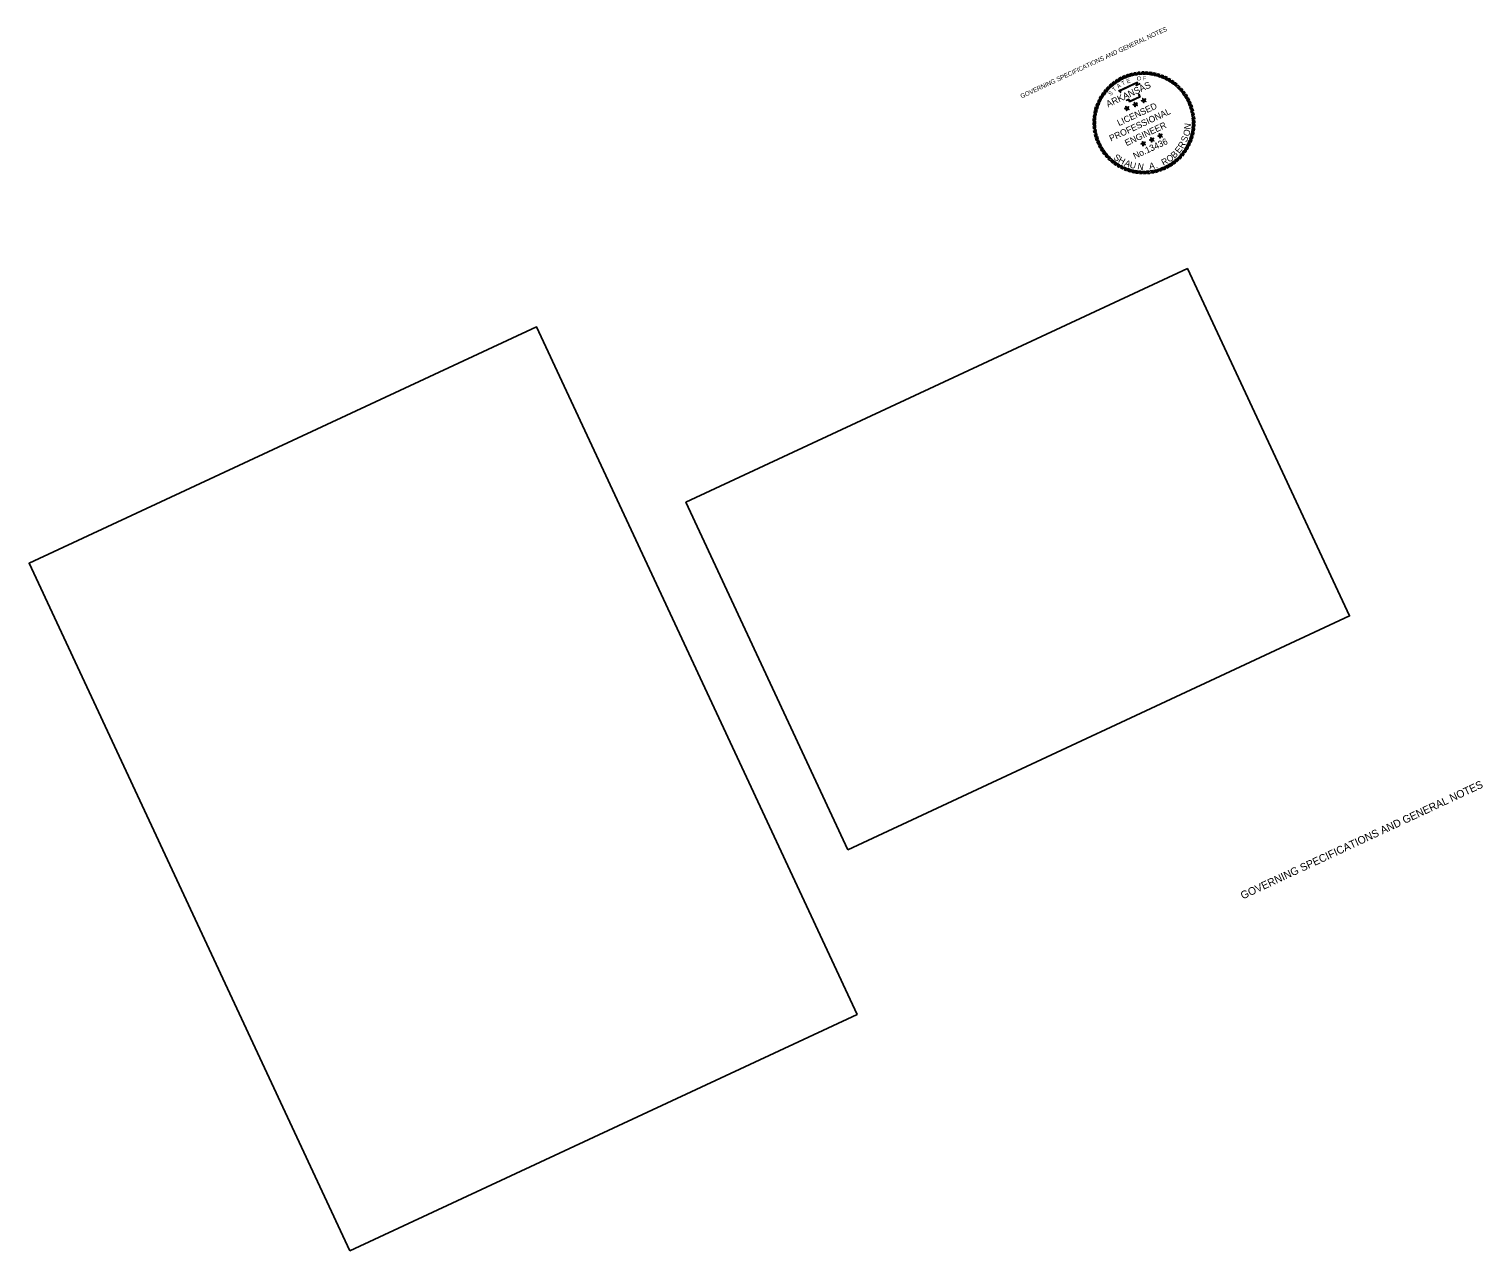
# Model space of a CAD drawing. Extents: x 757071 to 763666, y 1656563 to 1660766.
# Drawn here: x 760259 to 763666, y 1657902 to 1660766 of the extents above; entities that cross this region are included whole.
import ezdxf

# ---------------------------------------------------------------- set-up
doc = ezdxf.new("R2010")
doc.units = 0
for name, color, linetype in [('1', 7, 'Continuous'), ('60', 7, 'Continuous'), ('G-ANNO-SYMB', 7, 'Continuous')]:
    doc.layers.add(name, color=color, linetype=linetype)

msp = doc.modelspace()

# ---------------------------------------------------------------- linework, layer by layer
at = {"layer": '1'}
for points in [[(762178.2, 1658842.1), (763353.8, 1659390.3), (762973.9, 1660204.8), (761798.4, 1659656.7)], [(761010.6, 1657901.7), (762199.5, 1658456.1), (761447.8, 1660068.2), (760258.8, 1659513.8)]]:
    msp.add_lwpolyline(points, close=True, dxfattribs=at)
at = {"layer": 'G-ANNO-SYMB'}
for points in [[(762795, 1660637.6), (762791.2, 1660634.3), (762789.8, 1660625.2), (762793.7, 1660629.1)], [(762802.4, 1660643.4), (762798.3, 1660640.3), (762796.2, 1660631.4), (762800.4, 1660635)], [(762810.2, 1660648.6), (762805.9, 1660645.8), (762803.1, 1660637.1), (762807.6, 1660640.4)], [(762818.5, 1660653.1), (762813.9, 1660650.7), (762810.4, 1660642.2), (762815.2, 1660645.1)], [(762827, 1660657), (762822.3, 1660654.9), (762818.1, 1660646.8), (762823.1, 1660649.3)], [(762835.8, 1660660.1), (762830.9, 1660658.5), (762826.2, 1660650.7), (762831.3, 1660652.8)], [(762844.8, 1660662.6), (762839.9, 1660661.4), (762834.5, 1660654), (762839.8, 1660655.6)], [(762854, 1660664.4), (762849, 1660663.5), (762843, 1660656.6), (762848.4, 1660657.8)], [(762863.3, 1660665.4), (762858.2, 1660665), (762851.8, 1660658.5), (762857.2, 1660659.3)], [(762872.7, 1660665.7), (762867.6, 1660665.7), (762860.6, 1660659.7), (762866.1, 1660660.1)], [(762882.1, 1660665.3), (762876.9, 1660665.6), (762869.5, 1660660.3), (762875.1, 1660660.3)], [(762891.4, 1660664.2), (762886.3, 1660664.9), (762878.5, 1660660.1), (762884, 1660659.7)], [(762900.5, 1660662.3), (762895.5, 1660663.4), (762887.4, 1660659.2), (762892.9, 1660658.4)], [(762909.5, 1660659.7), (762904.6, 1660661.2), (762896.2, 1660657.7), (762901.6, 1660656.4)], [(762918.3, 1660656.4), (762913.5, 1660658.3), (762904.8, 1660655.4), (762910.1, 1660653.7)], [(762926.8, 1660652.4), (762922.2, 1660654.7), (762913.3, 1660652.5), (762918.4, 1660650.4)], [(762934.9, 1660647.8), (762930.5, 1660650.4), (762921.5, 1660649), (762926.4, 1660646.4)], [(762942.7, 1660642.5), (762938.5, 1660645.5), (762929.4, 1660644.8), (762934.1, 1660641.8)], [(762950, 1660636.7), (762946.1, 1660639.9), (762936.9, 1660639.9), (762941.4, 1660636.7)], [(762956.9, 1660630.3), (762953.2, 1660633.8), (762944.1, 1660634.6), (762948.3, 1660630.9)], [(762766, 1660601.3), (762763.7, 1660596.7), (762765.9, 1660587.8), (762768, 1660592.9)], [(762770.6, 1660609.4), (762768, 1660605), (762769.4, 1660596), (762772, 1660600.9)], [(762775.9, 1660617.2), (762772.9, 1660613), (762773.6, 1660603.9), (762776.5, 1660608.6)], [(762781.7, 1660624.5), (762778.4, 1660620.5), (762778.4, 1660611.4), (762781.7, 1660615.9)], [(762788.1, 1660631.3), (762784.5, 1660627.6), (762783.8, 1660618.5), (762787.4, 1660622.7)], [(762871.6, 1660598.7), (762869.8, 1660599.7), (762866.2, 1660598), (762870.1, 1660597.3)], [(762871.6, 1660598.7), (762872, 1660600.8), (762869.3, 1660603.7), (762869.8, 1660599.7)], [(762871.6, 1660598.7), (762873.7, 1660599), (762875.6, 1660602.4), (762872, 1660600.8)], [(762963.2, 1660623.3), (762959.8, 1660627.2), (762950.7, 1660628.6), (762954.6, 1660624.7)], [(762968.9, 1660616), (762965.8, 1660620.1), (762956.9, 1660622.2), (762960.5, 1660618)], [(762974.1, 1660608.1), (762971.3, 1660612.5), (762962.6, 1660615.3), (762965.9, 1660610.8)], [(762978.6, 1660599.9), (762976.2, 1660604.5), (762967.8, 1660608), (762970.6, 1660603.2)], [(762982.5, 1660591.4), (762980.4, 1660596.1), (762972.3, 1660600.3), (762974.8, 1660595.3)], [(762754.2, 1660565.8), (762753.5, 1660560.8), (762758.3, 1660553), (762758.7, 1660558.5)], [(762756.1, 1660575), (762755, 1660570), (762759.1, 1660561.9), (762760, 1660567.3)], [(762758.7, 1660584), (762757.2, 1660579.1), (762760.7, 1660570.7), (762762, 1660576.1)], [(762762, 1660592.8), (762760.1, 1660588), (762762.9, 1660579.3), (762764.7, 1660584.6)], [(762832.1, 1660580.3), (762830.3, 1660581.3), (762826.7, 1660579.6), (762830.6, 1660578.8)], [(762832.1, 1660580.3), (762832.5, 1660582.3), (762829.8, 1660585.2), (762830.3, 1660581.3)], [(762832.1, 1660580.3), (762830.6, 1660578.8), (762831.1, 1660574.9), (762833, 1660578.4)], [(762832.1, 1660580.3), (762834.2, 1660580.5), (762836.1, 1660584), (762832.5, 1660582.3)], [(762832.1, 1660580.3), (762833, 1660578.4), (762836.9, 1660577.6), (762834.2, 1660580.5)], [(762851.9, 1660589.5), (762850, 1660590.5), (762846.5, 1660588.8), (762850.3, 1660588.1)], [(762851.9, 1660589.5), (762852.3, 1660591.5), (762849.6, 1660594.4), (762850, 1660590.5)], [(762851.9, 1660589.5), (762850.3, 1660588.1), (762850.8, 1660584.1), (762852.7, 1660587.6)], [(762851.9, 1660589.5), (762853.9, 1660589.7), (762855.9, 1660593.2), (762852.3, 1660591.5)], [(762851.9, 1660589.5), (762852.7, 1660587.6), (762856.6, 1660586.8), (762853.9, 1660589.7)], [(762871.6, 1660598.7), (762870.1, 1660597.3), (762870.6, 1660593.4), (762872.5, 1660596.8)], [(762871.6, 1660598.7), (762872.5, 1660596.8), (762876.4, 1660596.1), (762873.7, 1660599)], [(762985.7, 1660582.6), (762984, 1660587.4), (762976.2, 1660592.2), (762978.3, 1660587.1)], [(762988.1, 1660573.6), (762986.9, 1660578.5), (762979.5, 1660583.9), (762981.2, 1660578.6)], [(762989.9, 1660564.3), (762989, 1660569.4), (762982.1, 1660575.3), (762983.4, 1660569.9)], [(762991, 1660555), (762990.5, 1660560.1), (762984, 1660566.6), (762984.9, 1660561.1)], [(762752.6, 1660547.2), (762752.7, 1660542.1), (762758.6, 1660535.1), (762758.2, 1660540.6)], [(762753.1, 1660556.5), (762752.7, 1660551.4), (762758.1, 1660544), (762758.1, 1660549.6)], [(762752.9, 1660537.8), (762753.4, 1660532.7), (762759.9, 1660526.2), (762759, 1660531.7)], [(762991.3, 1660545.7), (762991.2, 1660550.8), (762985.2, 1660557.8), (762985.7, 1660552.2)], [(762989.7, 1660527), (762990.4, 1660532.1), (762985.6, 1660539.9), (762985.2, 1660534.4)], [(762990.8, 1660536.3), (762991.2, 1660541.4), (762985.8, 1660548.8), (762985.8, 1660543.3)], [(762754, 1660528.5), (762754.9, 1660523.5), (762761.8, 1660517.5), (762760.5, 1660522.9)], [(762755.8, 1660519.3), (762757, 1660514.3), (762764.4, 1660509), (762762.7, 1660514.2)], [(762758.2, 1660510.3), (762759.9, 1660505.4), (762767.7, 1660500.6), (762765.6, 1660505.8)], [(762761.4, 1660501.5), (762763.5, 1660496.8), (762771.6, 1660492.6), (762769.1, 1660497.6)], [(762870.7, 1660497.5), (762868.9, 1660498.5), (762865.3, 1660496.8), (762869.2, 1660496)], [(762870.7, 1660497.5), (762871.1, 1660499.5), (762868.4, 1660502.4), (762868.9, 1660498.5)], [(762870.7, 1660497.5), (762869.2, 1660496), (762869.7, 1660492.1), (762871.6, 1660495.6)], [(762870.7, 1660497.5), (762872.8, 1660497.7), (762874.7, 1660501.2), (762871.1, 1660499.5)], [(762870.7, 1660497.5), (762871.6, 1660495.6), (762875.5, 1660494.8), (762872.8, 1660497.7)], [(762890.5, 1660506.7), (762888.7, 1660507.7), (762885.1, 1660506), (762889, 1660505.3)], [(762890.5, 1660506.7), (762890.9, 1660508.7), (762888.2, 1660511.6), (762888.7, 1660507.7)], [(762890.5, 1660506.7), (762889, 1660505.3), (762889.4, 1660501.3), (762891.4, 1660504.8)], [(762890.5, 1660506.7), (762892.5, 1660506.9), (762894.5, 1660510.4), (762890.9, 1660508.7)], [(762890.5, 1660506.7), (762891.4, 1660504.8), (762895.3, 1660504), (762892.5, 1660506.9)], [(762910.3, 1660515.9), (762908.4, 1660516.9), (762904.8, 1660515.2), (762908.7, 1660514.5)], [(762910.3, 1660515.9), (762910.7, 1660518), (762907.9, 1660520.9), (762908.4, 1660516.9)], [(762910.3, 1660515.9), (762908.7, 1660514.5), (762909.2, 1660510.6), (762911.1, 1660514)], [(762910.3, 1660515.9), (762912.3, 1660516.2), (762914.2, 1660519.6), (762910.7, 1660518)], [(762910.3, 1660515.9), (762911.1, 1660514), (762915, 1660513.3), (762912.3, 1660516.2)], [(762977.9, 1660491.6), (762980.2, 1660496.2), (762978, 1660505.1), (762975.9, 1660500)], [(762981.9, 1660500.1), (762983.8, 1660504.8), (762981, 1660513.5), (762979.2, 1660508.3)], [(762985.2, 1660508.8), (762986.7, 1660513.7), (762983.2, 1660522.2), (762981.9, 1660516.8)], [(762987.8, 1660517.8), (762988.9, 1660522.8), (762984.8, 1660531), (762983.9, 1660525.5)], [(762765.3, 1660492.9), (762767.7, 1660488.4), (762776.1, 1660484.9), (762773.3, 1660489.6)], [(762769.8, 1660484.7), (762772.6, 1660480.4), (762781.3, 1660477.6), (762778, 1660482.1)], [(762775, 1660476.9), (762778.1, 1660472.8), (762786.9, 1660470.7), (762783.4, 1660474.9)], [(762780.7, 1660469.5), (762784.1, 1660465.7), (762793.2, 1660464.2), (762789.2, 1660468.2)], [(762948.9, 1660455.2), (762952.7, 1660458.6), (762954.1, 1660467.6), (762950.2, 1660463.7)], [(762955.8, 1660461.5), (762959.4, 1660465.2), (762960.1, 1660474.3), (762956.5, 1660470.1)], [(762962.2, 1660468.4), (762965.5, 1660472.3), (762965.5, 1660481.5), (762962.2, 1660477)], [(762968, 1660475.7), (762971, 1660479.9), (762970.3, 1660489), (762967.4, 1660484.3)], [(762973.3, 1660483.4), (762975.9, 1660487.9), (762974.5, 1660496.9), (762971.9, 1660492)], [(762787, 1660462.6), (762790.7, 1660459), (762799.8, 1660458.3), (762795.6, 1660461.9)], [(762793.9, 1660456.2), (762797.8, 1660452.9), (762807, 1660452.9), (762802.5, 1660456.2)], [(762801.2, 1660450.3), (762805.4, 1660447.4), (762814.5, 1660448.1), (762809.8, 1660451)], [(762809, 1660445.1), (762813.4, 1660442.5), (762822.4, 1660443.9), (762817.5, 1660446.4)], [(762817.1, 1660440.5), (762821.7, 1660438.2), (762830.6, 1660440.3), (762825.5, 1660442.5)], [(762825.6, 1660436.5), (762830.4, 1660434.6), (762839.1, 1660437.4), (762833.8, 1660439.1)], [(762834.4, 1660433.2), (762839.3, 1660431.7), (762847.7, 1660435.2), (762842.3, 1660436.5)], [(762843.4, 1660430.6), (762848.4, 1660429.5), (762856.5, 1660433.6), (762851, 1660434.5)], [(762852.5, 1660428.7), (762857.6, 1660428), (762865.4, 1660432.8), (762859.9, 1660433.2)], [(762861.8, 1660427.5), (762867, 1660427.2), (762874.4, 1660432.6), (762868.8, 1660432.6)], [(762871.2, 1660427.1), (762876.3, 1660427.2), (762883.3, 1660433.1), (762877.8, 1660432.7)], [(762880.6, 1660427.4), (762885.7, 1660427.9), (762892.1, 1660434.4), (762886.7, 1660433.5)], [(762889.9, 1660428.5), (762894.9, 1660429.3), (762900.9, 1660436.3), (762895.5, 1660435)], [(762899.1, 1660430.2), (762904, 1660431.5), (762909.4, 1660438.9), (762904.1, 1660437.2)], [(762908.1, 1660432.7), (762913, 1660434.4), (762917.7, 1660442.2), (762912.6, 1660440.1)], [(762916.9, 1660435.9), (762921.6, 1660437.9), (762925.8, 1660446.1), (762920.8, 1660443.6)], [(762925.4, 1660439.8), (762930, 1660442.2), (762933.5, 1660450.6), (762928.7, 1660447.7)], [(762933.6, 1660444.3), (762938, 1660447), (762940.8, 1660455.7), (762936.3, 1660452.5)], [(762941.5, 1660449.5), (762945.6, 1660452.5), (762947.7, 1660461.4), (762943.5, 1660457.8)]]:
    msp.add_lwpolyline(points, close=True, dxfattribs=at)
for points in [[(762818, 1660616.8), (762813, 1660621.1), (762856.6, 1660641.5), (762855.1, 1660635.2), (762858, 1660636.6), (762860.5, 1660637.8), (762863.1, 1660638.7)], [(762818.5, 1660617.4), (762814.4, 1660620.9), (762855.5, 1660640.1), (762853.9, 1660633.8), (762858.3, 1660635.9), (762860.7, 1660637.1), (762863.3, 1660638)], [(762860.8, 1660614.5), (762860.3, 1660613.6), (762860.5, 1660612.5), (762861.3, 1660610.2), (762862.7, 1660607.2), (762838.3, 1660595.8), (762836.5, 1660599.9), (762836, 1660600.8), (762834.9, 1660600.6), (762831.4, 1660599), (762830.4, 1660599.7)], [(762860.1, 1660614.8), (762859.5, 1660613.7), (762859.7, 1660612.4), (762860.6, 1660609.9), (762861.7, 1660607.5), (762838.7, 1660596.8), (762837.1, 1660600.2), (762836.5, 1660601.6), (762834.7, 1660601.4), (762831.5, 1660599.9), (762830.8, 1660600.3)]]:
    msp.add_lwpolyline(points, dxfattribs=at)

# ---------------------------------------------------------------- texts
at = {"layer": '1'}
msp.add_text('GOVERNING SPECIFICATIONS AND GENERAL NOTES', height=10.552, rotation=25, dxfattribs=at).set_placement((762585.3, 1660603.3))
at = {"layer": '60'}
msp.add_text('GOVERNING SPECIFICATIONS AND GENERAL NOTES', height=18, rotation=25, dxfattribs=at).set_placement((763103.6, 1658725.6))
at = {"layer": 'G-ANNO-SYMB'}
for s, height, rotation, p in [('ARKANSAS', 15.49, 25, (762787.6, 1660582.3)), ('A', 9.49, 33.6788, (762811.8, 1660626.7)), ('T', 9.49, 26.4789, (762822.1, 1660633.6)), ('E', 9.49, 21.672, (762833.2, 1660638.5)), ('O', 9.49, 6.2218, (762855.5, 1660645.3)), ('F', 9.49, 0.3628, (762869.2, 1660646.1)), ('S', 9.49, 44.7726, (762794, 1660609.1)), ('T', 9.49, 41.9015, (762802.6, 1660619.1)), ('PROFESSIONAL', 15, 25, (762794.8, 1660502.2)), ('LICENSED', 15, 25, (762813.4, 1660538.5)), ('ENGINEER', 15, 25, (762831.3, 1660491.5)), ('N', 15, 81.1007, (762980.6, 1660529.9)), ('No.13436', 14.94, 25, (762850.7, 1660461.1)), ('R', 15, 60.6597, (762963.5, 1660484.8)), ('S', 15, 68.4878, (762971.7, 1660499.9)), ('O', 15, 69.7757, (762976.8, 1660513.3)), ('S', 15, 323.1636, (762799.2, 1660462.6)), ('H', 15, 330.619, (762810.3, 1660454.9)), ('R', 15, 28.2287, (762917.6, 1660445.5)), ('O', 15, 36.4296, (762931.1, 1660452.9)), ('B', 15, 43.885, (762943.4, 1660462.1)), ('E', 15, 52.8315, (762954.8, 1660473.5)), ('A', 15, 338.4472, (762824.8, 1660446.5)), ('U', 15, 345.9026, (762837.4, 1660441.6)), ('N', 15, 349.9326, (762855.8, 1660437.8)), ('A', 15, 8.0991, (762884.9, 1660437.2)), ('.', 15, 16.3, (762900.1, 1660439.5))]:
    msp.add_text(s, height=height, rotation=rotation, dxfattribs=at).set_placement(p)

doc.saveas('drawing.dxf')
